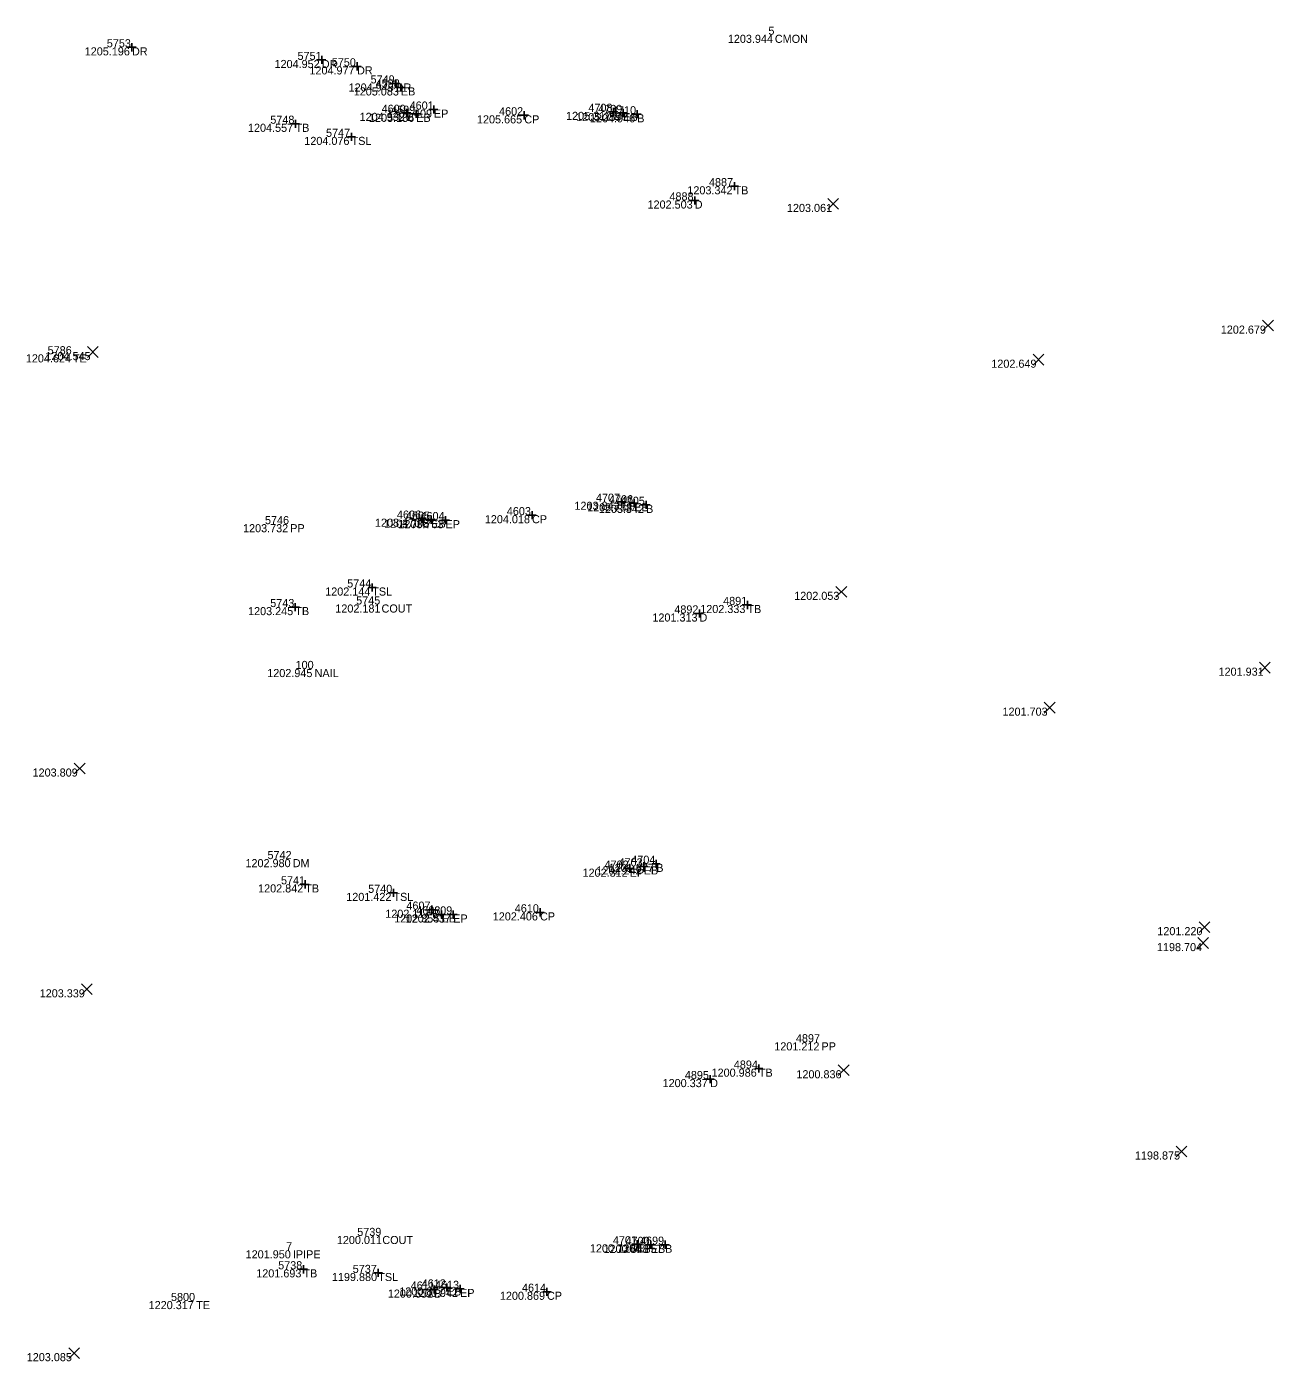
# Model space of a CAD drawing. Extents: x 2044997 to 2050342, y 455233 to 458054.
# Drawn here: x 2047579.5 to 2047733.5, y 456485 to 456649.9 of the extents above; entities that cross this region are included whole.
import ezdxf

# ---------------------------------------------------------------- set-up
doc = ezdxf.new("R2010")
doc.units = 0
for name, color, linetype in [('SV_X_Random_Point', 7, 'Continuous'), ('SV_X_Shot_Marker', 7, 'Continuous'), ('SV_X_Text_Comment', 7, 'Continuous'), ('SV_X_Text_Elevation', 7, 'Continuous'), ('SV_X_Text_Name', 7, 'Continuous')]:
    doc.layers.add(name, color=color, linetype=linetype)

msp = doc.modelspace()

# ---------------------------------------------------------------- linework, layer by layer
at = {"layer": 'SV_X_Random_Point'}
for p, q in [((2047678.46, 456627.3), (2047679.8, 456628.64)), ((2047678.46, 456628.64), (2047679.8, 456627.3)), ((2047732.16, 456612.27), (2047733.5, 456613.61)), ((2047732.16, 456613.61), (2047733.5, 456612.27)), ((2047586.99, 456609), (2047588.32, 456610.34)), ((2047586.99, 456610.34), (2047588.32, 456609)), ((2047703.81, 456608.06), (2047705.15, 456609.4)), ((2047703.81, 456609.4), (2047705.15, 456608.06)), ((2047679.47, 456579.39), (2047680.81, 456580.73)), ((2047679.47, 456580.73), (2047680.81, 456579.39)), ((2047731.78, 456570.02), (2047733.12, 456571.35)), ((2047731.78, 456571.35), (2047733.12, 456570.02)), ((2047705.2, 456565.08), (2047706.53, 456566.42)), ((2047705.2, 456566.42), (2047706.53, 456565.08)), ((2047585.37, 456557.56), (2047586.71, 456558.89)), ((2047585.37, 456558.89), (2047586.71, 456557.56)), ((2047724.34, 456537.97), (2047725.67, 456539.31)), ((2047724.34, 456539.31), (2047725.67, 456537.97)), ((2047724.16, 456536), (2047725.49, 456537.34)), ((2047724.16, 456537.34), (2047725.49, 456536)), ((2047586.25, 456530.3), (2047587.59, 456531.63)), ((2047586.25, 456531.63), (2047587.59, 456530.3)), ((2047679.76, 456520.29), (2047681.09, 456521.62)), ((2047679.76, 456521.62), (2047681.09, 456520.29)), ((2047721.48, 456510.26), (2047722.81, 456511.6)), ((2047721.48, 456511.6), (2047722.81, 456510.26)), ((2047584.68, 456485.35), (2047586.02, 456486.69)), ((2047584.68, 456486.69), (2047586.02, 456485.35))]:
    msp.add_line(p, q, dxfattribs=at)
at = {"layer": 'SV_X_Shot_Marker'}
for p, q in [((2047592.5, 456647.81), (2047592.5, 456646.81)), ((2047592, 456647.31), (2047593, 456647.31)), ((2047592.5, 456647.31), (2047592.5, 456647.31)), ((2047615.95, 456646.25), (2047615.95, 456645.25)), ((2047615.45, 456645.75), (2047616.45, 456645.75)), ((2047615.95, 456645.75), (2047615.95, 456645.75)), ((2047619.8, 456644.96), (2047620.8, 456644.96)), ((2047620.3, 456645.46), (2047620.3, 456644.46)), ((2047620.3, 456644.96), (2047620.3, 456644.96)), ((2047624.58, 456642.85), (2047625.58, 456642.85)), ((2047625.08, 456643.35), (2047625.08, 456642.35)), ((2047625.08, 456642.85), (2047625.08, 456642.85)), ((2047625.72, 456642.86), (2047625.72, 456641.86)), ((2047625.22, 456642.36), (2047626.22, 456642.36)), ((2047625.72, 456642.36), (2047625.72, 456642.36)), ((2047625.96, 456639.22), (2047626.96, 456639.22)), ((2047626.46, 456639.72), (2047626.46, 456638.72)), ((2047626.46, 456639.22), (2047626.46, 456639.22)), ((2047627.62, 456639.6), (2047627.62, 456638.6)), ((2047629.3, 456639.62), (2047630.3, 456639.62)), ((2047629.8, 456640.12), (2047629.8, 456639.12)), ((2047629.8, 456639.62), (2047629.8, 456639.62)), ((2047640.97, 456639.41), (2047640.97, 456638.41)), ((2047651.5, 456639.34), (2047652.5, 456639.34)), ((2047652, 456639.84), (2047652, 456638.84)), ((2047652, 456639.34), (2047652, 456639.34)), ((2047652.69, 456639.2), (2047653.69, 456639.2)), ((2047653.19, 456639.7), (2047653.19, 456638.7)), ((2047653.19, 456639.2), (2047653.19, 456639.2)), ((2047654.92, 456639.54), (2047654.92, 456638.54)), ((2047612.21, 456637.87), (2047613.21, 456637.87)), ((2047612.71, 456638.37), (2047612.71, 456637.37)), ((2047612.71, 456637.87), (2047612.71, 456637.87)), ((2047627.12, 456639.1), (2047628.12, 456639.1)), ((2047627.62, 456639.1), (2047627.62, 456639.1)), ((2047640.47, 456638.91), (2047641.47, 456638.91)), ((2047640.97, 456638.91), (2047640.97, 456638.91)), ((2047654.42, 456639.04), (2047655.42, 456639.04)), ((2047654.92, 456639.04), (2047654.92, 456639.04)), ((2047619.13, 456636.25), (2047620.13, 456636.25)), ((2047619.63, 456636.75), (2047619.63, 456635.75)), ((2047619.63, 456636.25), (2047619.63, 456636.25)), ((2047666.44, 456630.15), (2047667.44, 456630.15)), ((2047666.94, 456630.65), (2047666.94, 456629.65)), ((2047666.94, 456630.15), (2047666.94, 456630.15)), ((2047661.52, 456628.39), (2047662.52, 456628.39)), ((2047662.02, 456628.89), (2047662.02, 456627.89)), ((2047662.02, 456628.39), (2047662.02, 456628.39)), ((2047652.99, 456591.68), (2047652.99, 456590.68)), ((2047654.55, 456591.49), (2047654.55, 456590.49)), ((2047641.92, 456590.02), (2047641.92, 456589.02)), ((2047652.49, 456591.18), (2047653.49, 456591.18)), ((2047652.99, 456591.18), (2047652.99, 456591.18)), ((2047654.05, 456590.99), (2047655.05, 456590.99)), ((2047654.55, 456590.99), (2047654.55, 456590.99)), ((2047655.51, 456590.8), (2047656.51, 456590.8)), ((2047656.01, 456591.3), (2047656.01, 456590.3)), ((2047656.01, 456590.8), (2047656.01, 456590.8)), ((2047627.86, 456589.09), (2047628.86, 456589.09)), ((2047628.36, 456589.59), (2047628.36, 456588.59)), ((2047628.36, 456589.09), (2047628.36, 456589.09)), ((2047628.97, 456588.97), (2047629.97, 456588.97)), ((2047629.47, 456589.47), (2047629.47, 456588.47)), ((2047629.47, 456588.97), (2047629.47, 456588.97)), ((2047630.73, 456588.91), (2047631.73, 456588.91)), ((2047631.23, 456589.41), (2047631.23, 456588.41)), ((2047631.23, 456588.91), (2047631.23, 456588.91)), ((2047641.42, 456589.52), (2047642.42, 456589.52)), ((2047641.92, 456589.52), (2047641.92, 456589.52)), ((2047621.68, 456580.59), (2047622.68, 456580.59)), ((2047622.18, 456581.09), (2047622.18, 456580.09)), ((2047622.18, 456580.59), (2047622.18, 456580.59)), ((2047612.68, 456578.67), (2047612.68, 456577.67)), ((2047668.03, 456578.43), (2047669.03, 456578.43)), ((2047668.53, 456578.93), (2047668.53, 456577.93)), ((2047668.53, 456578.43), (2047668.53, 456578.43)), ((2047612.18, 456578.17), (2047613.18, 456578.17)), ((2047612.68, 456578.17), (2047612.68, 456578.17)), ((2047662.11, 456577.38), (2047663.11, 456577.38)), ((2047662.61, 456577.88), (2047662.61, 456576.88)), ((2047662.61, 456577.38), (2047662.61, 456577.38)), ((2047657.27, 456546.96), (2047657.27, 456545.96)), ((2047653.49, 456545.86), (2047654.49, 456545.86)), ((2047653.99, 456546.36), (2047653.99, 456545.36)), ((2047653.99, 456545.86), (2047653.99, 456545.86)), ((2047655.22, 456546.14), (2047656.22, 456546.14)), ((2047655.72, 456546.64), (2047655.72, 456545.64)), ((2047655.72, 456546.14), (2047655.72, 456546.14)), ((2047656.77, 456546.46), (2047657.77, 456546.46)), ((2047657.27, 456546.46), (2047657.27, 456546.46)), ((2047613.41, 456543.92), (2047614.41, 456543.92)), ((2047613.91, 456544.42), (2047613.91, 456543.42)), ((2047613.91, 456543.92), (2047613.91, 456543.92)), ((2047624.3, 456542.87), (2047625.3, 456542.87)), ((2047624.8, 456543.37), (2047624.8, 456542.37)), ((2047624.8, 456542.87), (2047624.8, 456542.87)), ((2047629.06, 456540.79), (2047630.06, 456540.79)), ((2047629.56, 456541.29), (2047629.56, 456540.29)), ((2047629.56, 456540.79), (2047629.56, 456540.79)), ((2047630.74, 456540.71), (2047630.74, 456539.71)), ((2047632.19, 456540.7), (2047632.19, 456539.7)), ((2047642.41, 456540.46), (2047643.41, 456540.46)), ((2047642.91, 456540.96), (2047642.91, 456539.96)), ((2047642.91, 456540.46), (2047642.91, 456540.46)), ((2047630.24, 456540.21), (2047631.24, 456540.21)), ((2047630.74, 456540.21), (2047630.74, 456540.21)), ((2047631.69, 456540.2), (2047632.69, 456540.2)), ((2047632.19, 456540.2), (2047632.19, 456540.2)), ((2047669.44, 456521.16), (2047670.44, 456521.16)), ((2047669.94, 456521.66), (2047669.94, 456520.66)), ((2047669.94, 456521.16), (2047669.94, 456521.16)), ((2047663.43, 456519.87), (2047664.43, 456519.87)), ((2047663.93, 456520.37), (2047663.93, 456519.37)), ((2047663.93, 456519.87), (2047663.93, 456519.87)), ((2047654.41, 456499.46), (2047655.41, 456499.46)), ((2047654.91, 456499.96), (2047654.91, 456498.96)), ((2047654.91, 456499.46), (2047654.91, 456499.46)), ((2047656.09, 456499.39), (2047657.09, 456499.39)), ((2047656.59, 456499.89), (2047656.59, 456498.89)), ((2047656.59, 456499.39), (2047656.59, 456499.39)), ((2047657.86, 456499.41), (2047658.86, 456499.41)), ((2047658.36, 456499.91), (2047658.36, 456498.91)), ((2047658.36, 456499.41), (2047658.36, 456499.41)), ((2047613.18, 456496.37), (2047614.18, 456496.37)), ((2047613.68, 456496.87), (2047613.68, 456495.87)), ((2047613.68, 456496.37), (2047613.68, 456496.37)), ((2047622.43, 456495.92), (2047623.43, 456495.92)), ((2047622.93, 456496.42), (2047622.93, 456495.42)), ((2047622.93, 456495.92), (2047622.93, 456495.92)), ((2047629.83, 456494.37), (2047629.83, 456493.37)), ((2047630.9, 456494.13), (2047631.9, 456494.13)), ((2047631.4, 456494.63), (2047631.4, 456493.63)), ((2047631.4, 456494.13), (2047631.4, 456494.13)), ((2047633.03, 456494.45), (2047633.03, 456493.45)), ((2047629.33, 456493.87), (2047630.33, 456493.87)), ((2047629.83, 456493.87), (2047629.83, 456493.87)), ((2047632.53, 456493.95), (2047633.53, 456493.95)), ((2047633.03, 456493.95), (2047633.03, 456493.95)), ((2047643.27, 456493.6), (2047644.27, 456493.6)), ((2047643.77, 456494.1), (2047643.77, 456493.1)), ((2047643.77, 456493.6), (2047643.77, 456493.6))]:
    msp.add_line(p, q, dxfattribs=at)

# ---------------------------------------------------------------- texts
at = {"layer": 'SV_X_Text_Comment'}
for s, p in [('CMON', (2047671.92, 456647.86)), ('DR', (2047592.5, 456646.31)), ('DR', (2047615.95, 456644.75)), ('DR', (2047620.3, 456643.96)), ('DR', (2047625.08, 456641.85)), ('EB', (2047625.72, 456641.36)), ('B', (2047626.46, 456638.22)), ('EP', (2047629.8, 456638.62)), ('EP', (2047652, 456638.34)), ('EB', (2047653.19, 456638.2)), ('TB', (2047612.71, 456636.87)), ('EB', (2047627.62, 456638.1)), ('CP', (2047640.97, 456637.91)), ('B', (2047654.92, 456638.04)), ('TSL', (2047619.63, 456635.25)), ('TB', (2047666.94, 456629.15)), ('D', (2047662.02, 456627.39)), ('TE', (2047585.2, 456608.39)), ('EP', (2047652.99, 456590.18)), ('EB', (2047654.55, 456589.99)), ('B', (2047656.01, 456589.8)), ('PP', (2047612.05, 456587.41)), ('B', (2047628.36, 456588.09)), ('EB', (2047629.47, 456587.97)), ('EP', (2047631.23, 456587.91)), ('CP', (2047641.92, 456588.52)), ('TSL', (2047622.18, 456579.59)), ('COUT', (2047623.33, 456577.49)), ('TB', (2047668.53, 456577.43)), ('TB', (2047612.68, 456577.17)), ('D', (2047662.61, 456576.38)), ('NAIL', (2047615.06, 456569.52)), ('DM', (2047612.36, 456546.04)), ('EP', (2047653.99, 456544.86)), ('EB', (2047655.72, 456545.14)), ('B', (2047657.27, 456545.46)), ('TB', (2047613.91, 456542.92)), ('TSL', (2047624.8, 456541.87)), ('B', (2047629.56, 456539.79)), ('CP', (2047642.91, 456539.46)), ('EB', (2047630.74, 456539.21)), ('EP', (2047632.19, 456539.2)), ('PP', (2047677.68, 456523.41)), ('TB', (2047669.94, 456520.16)), ('D', (2047663.93, 456518.87)), ('COUT', (2047623.43, 456499.49)), ('EP', (2047654.91, 456498.46)), ('EB', (2047656.59, 456498.39)), ('B', (2047658.36, 456498.41)), ('IPIPE', (2047612.38, 456497.72)), ('TB', (2047613.68, 456495.37)), ('TSL', (2047622.93, 456494.92)), ('EB', (2047631.4, 456493.13)), ('B', (2047629.83, 456492.87)), ('EP', (2047633.03, 456492.95)), ('CP', (2047643.77, 456492.6)), ('TE', (2047600.44, 456491.45))]:
    msp.add_text(s, height=1, dxfattribs=at).set_placement(p)
at = {"layer": 'SV_X_Text_Elevation'}
for s, p in [('1203.944', (2047666.11, 456647.86)), ('1205.196', (2047586.66, 456646.31)), ('1204.952', (2047610.11, 456644.75)), ('1204.977', (2047614.42, 456643.96)), ('1204.949', (2047619.26, 456641.85)), ('1205.083', (2047619.89, 456641.36)), ('1204.932', (2047620.62, 456638.22)), ('1205.409', (2047623.99, 456638.62)), ('1205.317', (2047646.12, 456638.34)), ('1205.259', (2047647.37, 456638.2)), ('1204.557', (2047606.83, 456636.87)), ('1205.186', (2047621.78, 456638.1)), ('1205.665', (2047635.12, 456637.91)), ('1204.946', (2047649.08, 456638.04)), ('1204.076', (2047613.79, 456635.25)), ('1203.342', (2047661.11, 456629.15)), ('1202.503', (2047656.19, 456627.39)), ('1203.061', (2047673.41, 456626.97)), ('1202.679', (2047727.01, 456611.94)), ('1204.545', (2047581.81, 456608.67)), ('1204.624', (2047579.39, 456608.39)), ('1202.649', (2047698.66, 456607.73)), ('1203.843', (2047647.16, 456590.18)), ('1203.738', (2047648.72, 456589.99)), ('1203.342', (2047650.17, 456589.8)), ('1203.732', (2047606.22, 456587.41)), ('1203.470', (2047622.52, 456588.09)), ('1203.708', (2047623.64, 456587.97)), ('1203.763', (2047625.4, 456587.91)), ('1204.018', (2047636.09, 456588.52)), ('1202.144', (2047616.37, 456579.59)), ('1202.053', (2047674.31, 456579.06)), ('1202.181', (2047617.62, 456577.49)), ('1202.333', (2047662.7, 456577.43)), ('1203.245', (2047606.84, 456577.17)), ('1201.313', (2047656.79, 456576.38)), ('1202.945', (2047609.21, 456569.52)), ('1201.931', (2047726.73, 456569.69)), ('1201.703', (2047700.04, 456564.75)), ('1203.809', (2047580.22, 456557.23)), ('1202.980', (2047606.52, 456546.04)), ('1202.312', (2047648.16, 456544.86)), ('1202.242', (2047649.88, 456545.14)), ('1201.877', (2047651.39, 456545.46)), ('1202.842', (2047608.08, 456542.92)), ('1201.422', (2047618.97, 456541.87)), ('1202.117', (2047623.79, 456539.79)), ('1202.406', (2047637.07, 456539.46)), ('1202.355', (2047624.89, 456539.21)), ('1202.437', (2047626.31, 456539.2)), ('1201.220', (2047719.17, 456537.64)), ('1198.704', (2047719.12, 456535.67)), ('1203.339', (2047581.1, 456529.96)), ('1201.212', (2047671.85, 456523.41)), ('1200.986', (2047664.1, 456520.16)), ('1200.836', (2047674.58, 456519.96)), ('1200.337', (2047658.05, 456518.87)), ('1198.875', (2047716.4, 456509.93)), ('1200.011', (2047617.81, 456499.49)), ('1200.736', (2047649.07, 456498.46)), ('1200.648', (2047650.75, 456498.39)), ('1200.357', (2047652.48, 456498.41)), ('1201.950', (2047606.54, 456497.72)), ('1201.693', (2047607.85, 456495.37)), ('1199.880', (2047617.2, 456494.92)), ('1200.877', (2047625.52, 456493.13)), ('1200.651', (2047624.11, 456492.87)), ('1200.942', (2047627.2, 456492.95)), ('1200.869', (2047637.95, 456492.6)), ('1220.317', (2047594.56, 456491.45)), ('1203.085', (2047579.5, 456485.02))]:
    msp.add_text(s, height=1, dxfattribs=at).set_placement(p)
at = {"layer": 'SV_X_Text_Name'}
for s, p in [('5', (2047671.12, 456648.86)), ('5753', (2047589.39, 456647.31)), ('5751', (2047612.95, 456645.75)), ('5750', (2047617.18, 456644.96)), ('5749', (2047621.98, 456642.85)), ('4598', (2047622.6, 456642.36)), ('4600', (2047623.34, 456639.22)), ('4599', (2047624.52, 456639.1)), ('4601', (2047626.8, 456639.62)), ('4602', (2047637.85, 456638.91)), ('4708', (2047648.88, 456639.34)), ('4709', (2047650.09, 456639.2)), ('4710', (2047651.8, 456639.04)), ('5748', (2047609.59, 456637.87)), ('5747', (2047616.47, 456636.25)), ('4887', (2047663.78, 456630.15)), ('4888', (2047658.9, 456628.39)), ('5786', (2047582.08, 456609.39)), ('4707', (2047649.82, 456591.18)), ('4706', (2047651.43, 456590.99)), ('4705', (2047652.88, 456590.8)), ('4606', (2047625.23, 456589.09)), ('4605', (2047626.34, 456588.97)), ('4604', (2047628.14, 456588.91)), ('4603', (2047638.81, 456589.52)), ('5746', (2047608.93, 456588.41)), ('5744', (2047619.09, 456580.59)), ('5743', (2047609.58, 456578.17)), ('5745', (2047620.2, 456578.49)), ('4892', (2047659.5, 456577.38)), ('4891', (2047665.53, 456578.43)), ('100', (2047612.71, 456570.52)), ('5742', (2047609.24, 456547.04)), ('4702', (2047650.88, 456545.86)), ('4703', (2047652.61, 456546.14)), ('4704', (2047654.18, 456546.46)), ('5741', (2047610.91, 456543.92)), ('5740', (2047621.68, 456542.87)), ('4607', (2047626.4, 456540.79)), ('4608', (2047627.62, 456540.21)), ('4609', (2047629.09, 456540.2)), ('4610', (2047639.79, 456540.46)), ('4897', (2047674.52, 456524.41)), ('4894', (2047666.85, 456521.16)), ('4895', (2047660.8, 456519.87)), ('5739', (2047620.33, 456500.49)), ('7', (2047611.54, 456498.72)), ('4701', (2047651.91, 456499.46)), ('4700', (2047653.47, 456499.39)), ('4699', (2047655.26, 456499.41)), ('5738', (2047610.56, 456496.37)), ('5737', (2047619.77, 456495.92)), ('4611', (2047626.93, 456493.87)), ('4612', (2047628.29, 456494.13)), ('4613', (2047629.93, 456493.95)), ('4614', (2047640.68, 456493.6)), ('5800', (2047597.32, 456492.45))]:
    msp.add_text(s, height=1, dxfattribs=at).set_placement(p)

doc.saveas('drawing.dxf')
